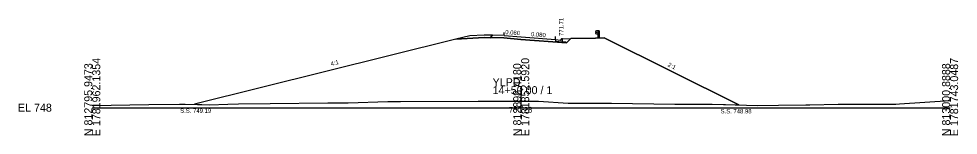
# Model space of a CAD drawing. Extents: x -26 to 353, y -10 to 9080.
# Drawn here: x -25.7 to 302.8, y 4490.3 to 4531.3 of the extents above; entities that cross this region are included whole.
import ezdxf

# ---------------------------------------------------------------- set-up
doc = ezdxf.new("R2010")
doc.units = 0
for name, color, linetype in [('Exist Cross Section Cell', 7, 'Continuous'), ('Exist XS Center Line Elevation Label', 7, 'Continuous'), ('Exist XS Ground Line', 7, 'Continuous'), ('Prop XS Dump Level', 7, 'Continuous'), ('Prop XS Earthwork Shape', 7, 'Continuous'), ('Prop XS EOT Tick Mark', 7, 'Continuous'), ('Prop XS Finish Grade', 7, 'Continuous'), ('Prop XS Finish Grade CurbGutter', 7, 'Continuous'), ('Prop XS Finish Grade Earthwork', 7, 'Continuous'), ('Prop XS Finish Grade Paved Shoulder', 7, 'Continuous'), ('Prop XS Finish Grade Pavement', 7, 'Continuous'), ('Prop XS Guardrail', 7, 'Continuous'), ('Prop XS Hydro Elevations', 7, 'Continuous'), ('Prop XS Pvmt Edge Slope', 7, 'Continuous'), ('Prop XS SE Text', 7, 'Continuous'), ('Prop XS Side Slope Text', 7, 'Continuous'), ('Prop XS SS Elevation Text', 7, 'Continuous'), ('Prop XS Subgrade CurbGutter', 7, 'Continuous'), ('Prop XS Subgrade Earthwork', 7, 'Continuous'), ('Scratch_Level_3', 7, 'Continuous')]:
    doc.layers.add(name, color=color, linetype=linetype)

msp = doc.modelspace()

# ---------------------------------------------------------------- linework, layer by layer
at = {"layer": 'Exist Cross Section Cell'}
for p, q in [((150, 4500), (150, 4507.56)), ((0, 4500), (150, 4500)), ((150, 4500), (300, 4500))]:
    msp.add_line(p, q, dxfattribs=at)
at = {"layer": 'Exist XS Ground Line'}
for p, q in [((0, 4500.8), (19.82, 4501.11)), ((19.82, 4501.11), (30.48, 4501.28)), ((30.48, 4501.28), (32.54, 4501.28)), ((32.54, 4501.28), (41.06, 4501.04)), ((41.06, 4501.04), (47.36, 4501.18)), ((47.36, 4501.18), (51.2, 4501.34)), ((51.2, 4501.34), (62.23, 4501.47)), ((62.23, 4501.47), (82.41, 4501.66)), ((82.41, 4501.66), (89.49, 4501.76)), ((89.49, 4501.76), (103.34, 4502.14)), ((103.34, 4502.14), (107.77, 4502.19)), ((107.77, 4502.19), (134.91, 4502.26)), ((134.91, 4502.26), (135.45, 4502.28)), ((135.45, 4502.28), (136.98, 4502.3)), ((136.98, 4502.3), (138.66, 4502.29)), ((138.66, 4502.29), (150, 4502.28)), ((150, 4502.28), (156.08, 4502.28)), ((156.08, 4502.28), (166.39, 4501.54)), ((166.39, 4501.54), (170.73, 4501.59)), ((170.73, 4501.59), (181.55, 4501.56)), ((181.55, 4501.56), (203.68, 4501.25)), ((203.68, 4501.25), (204.11, 4501.25)), ((204.11, 4501.25), (209.96, 4501.24)), ((209.96, 4501.24), (216.75, 4501.24)), ((216.75, 4501.24), (232.81, 4500.79)), ((232.81, 4500.79), (239.97, 4500.91)), ((239.97, 4500.91), (249.6, 4501.06)), ((249.6, 4501.06), (250.96, 4501.05)), ((250.96, 4501.05), (260.83, 4501.23)), ((260.83, 4501.23), (279.59, 4501.24)), ((279.59, 4501.24), (281, 4501.23)), ((281, 4501.23), (282.27, 4501.3)), ((282.27, 4501.3), (300, 4502.52))]:
    msp.add_line(p, q, dxfattribs=at)
at = {"layer": 'Prop XS Dump Level'}
for p, q in [((144, 4525.39), (150, 4524.91)), ((150, 4524.91), (162, 4523.95))]:
    msp.add_line(p, q, dxfattribs=at)
at = {"layer": 'Prop XS Earthwork Shape'}
msp.add_lwpolyline([(127.17, 4524.03), (35.81, 4501.19), (41.06, 4501.04), (47.36, 4501.18), (51.2, 4501.34), (62.23, 4501.47), (82.41, 4501.66), (89.49, 4501.76), (103.34, 4502.14), (107.77, 4502.19), (134.91, 4502.26), (135.45, 4502.28), (136.98, 4502.3), (138.66, 4502.29), (150, 4502.28), (156.08, 4502.28), (166.39, 4501.54), (170.73, 4501.59), (181.55, 4501.56), (203.68, 4501.25), (204.11, 4501.25), (209.96, 4501.24), (216.75, 4501.24), (226.08, 4500.98), (179, 4524.51), (176, 4524.45), (167.39, 4524.27), (165.84, 4522.73), (149.93, 4524), (143.95, 4524.48), (139.1, 4524.58), (137.02, 4524.62)], close=True, dxfattribs=at)
at = {"layer": 'Prop XS EOT Tick Mark'}
for p, q in [((144, 4525.39), (144, 4526.39)), ((162, 4523.95), (162, 4524.95))]:
    msp.add_line(p, q, dxfattribs=at)
at = {"layer": 'Prop XS Finish Grade'}
for p, q in [((132, 4525.23), (127.17, 4524.03)), ((137, 4525.53), (132, 4525.23)), ((140, 4525.47), (137, 4525.53)), ((164.5, 4524.21), (167.39, 4524.27))]:
    msp.add_line(p, q, dxfattribs=at)
at = {"layer": 'Prop XS Finish Grade CurbGutter'}
for p, q in [((162, 4523.95), (163.75, 4523.74)), ((163.97, 4523.86), (164.03, 4524.11)), ((164.03, 4524.11), (164.12, 4524.2)), ((164.25, 4524.21), (164.12, 4524.2)), ((164.5, 4524.21), (164.25, 4524.21)), ((163.75, 4523.74), (163.87, 4523.77)), ((163.87, 4523.77), (163.97, 4523.86))]:
    msp.add_line(p, q, dxfattribs=at)
at = {"layer": 'Prop XS Finish Grade Earthwork'}
for p, q in [((127.17, 4524.03), (35.81, 4501.19)), ((167.39, 4524.27), (176, 4524.45)), ((176, 4524.45), (179, 4524.51)), ((179, 4524.51), (226.08, 4500.98))]:
    msp.add_line(p, q, dxfattribs=at)
at = {"layer": 'Prop XS Finish Grade Paved Shoulder'}
msp.add_line((144, 4525.39), (140, 4525.47), dxfattribs=at)
at = {"layer": 'Prop XS Finish Grade Pavement'}
for p, q in [((144, 4525.39), (150, 4524.91)), ((150, 4524.91), (162, 4523.95))]:
    msp.add_line(p, q, dxfattribs=at)
at = {"layer": 'Prop XS Guardrail'}
for p, q in [((176.03, 4526.83), (176, 4526.77)), ((176, 4526.77), (176.03, 4526.71)), ((176.03, 4526.22), (176, 4526.16)), ((176, 4526.16), (176.03, 4526.1)), ((176.32, 4527.03), (176.03, 4526.83)), ((176.03, 4526.71), (176.32, 4526.51)), ((176.32, 4526.42), (176.03, 4526.22)), ((176.03, 4526.1), (176.32, 4525.9)), ((176.82, 4527.03), (176.32, 4527.03)), ((176.32, 4526.51), (176.32, 4526.42)), ((176.32, 4525.9), (176.82, 4525.9)), ((177.32, 4527.03), (176.82, 4527.03)), ((176.82, 4527.03), (176.82, 4524.53)), ((177.32, 4527.03), (177.32, 4524.53))]:
    msp.add_line(p, q, dxfattribs=at)
at = {"layer": 'Prop XS Pvmt Edge Slope'}
for p, q in [((140, 4525.47), (139.1, 4524.58)), ((164.5, 4523.17), (165.5, 4523.09)), ((165.5, 4523.09), (165.84, 4522.73))]:
    msp.add_line(p, q, dxfattribs=at)
at = {"layer": 'Prop XS Subgrade CurbGutter'}
for p, q in [((162, 4523.95), (162, 4523.37)), ((164.5, 4523.17), (164.5, 4524.21)), ((162, 4523.37), (164.5, 4523.17))]:
    msp.add_line(p, q, dxfattribs=at)
at = {"layer": 'Prop XS Subgrade Earthwork'}
for p, q in [((137.02, 4524.62), (127.17, 4524.03)), ((139.1, 4524.58), (137.02, 4524.62)), ((143.95, 4524.48), (139.1, 4524.58)), ((143.95, 4524.48), (149.93, 4524)), ((149.93, 4524), (165.84, 4522.73)), ((165.84, 4522.73), (167.39, 4524.27))]:
    msp.add_line(p, q, dxfattribs=at)
at = {"layer": 'Scratch_Level_3'}
for p, q in [((132, 4525.23), (127.17, 4524.03)), ((127.17, 4524.03), (137.02, 4524.62)), ((137, 4525.53), (132, 4525.23)), ((140, 4525.47), (137, 4525.53)), ((137.02, 4524.62), (139.1, 4524.58)), ((139.1, 4524.58), (140, 4525.47))]:
    msp.add_line(p, q, dxfattribs=at)

# ---------------------------------------------------------------- texts
at = {"layer": 'Exist Cross Section Cell'}
for s, p in [('E 1781962.1354', (2.8, 4490)), ('E 1781852.5920', (152.8, 4490)), ('N 812795.9473', (0, 4490)), ('N 812898.4180', (150, 4490)), ('N 813000.8888', (300, 4490)), ('E 1781743.0487', (302.8, 4490))]:
    msp.add_text(s, height=2.8, rotation=90, dxfattribs=at).set_placement(p)
for s, p in [('YLPD', (140, 4507.56)), ('14+50.00 / 1', (140, 4504.76)), ('EL 748', (-26, 4498.6))]:
    msp.add_text(s, height=2.8, dxfattribs=at).set_placement(p)
at = {"layer": 'Exist XS Center Line Elevation Label'}
msp.add_text('750.28', height=2, dxfattribs=at).set_placement((145.73, 4498.28))
at = {"layer": 'Prop XS Dump Level'}
msp.add_text('Case4', height=0.04, dxfattribs=at).set_placement((132, 4525.19))
at = {"layer": 'Prop XS Hydro Elevations'}
msp.add_text('771.71', height=1.5, rotation=90, dxfattribs=at).set_placement((164.75, 4525.21))
at = {"layer": 'Prop XS SE Text'}
for p in [(144.38, 4525.86), (153.38, 4525.14)]:
    msp.add_text('0.080', height=1.5, rotation=355.4261, dxfattribs=at).set_placement(p)
at = {"layer": 'Prop XS Side Slope Text'}
for s, rotation, p in [('4:1', 14.0362, (83.54, 4514.67)), ('2:1', 333.4349, (201.1, 4514.62))]:
    msp.add_text(s, height=1.5, rotation=rotation, dxfattribs=at).set_placement(p)
at = {"layer": 'Prop XS SS Elevation Text'}
for s, p in [('S.S. 749.19', (30.77, 4498.19)), ('S.S. 748.98', (219.75, 4498.01))]:
    msp.add_text(s, height=1.5, dxfattribs=at).set_placement(p)

doc.saveas('drawing.dxf')
